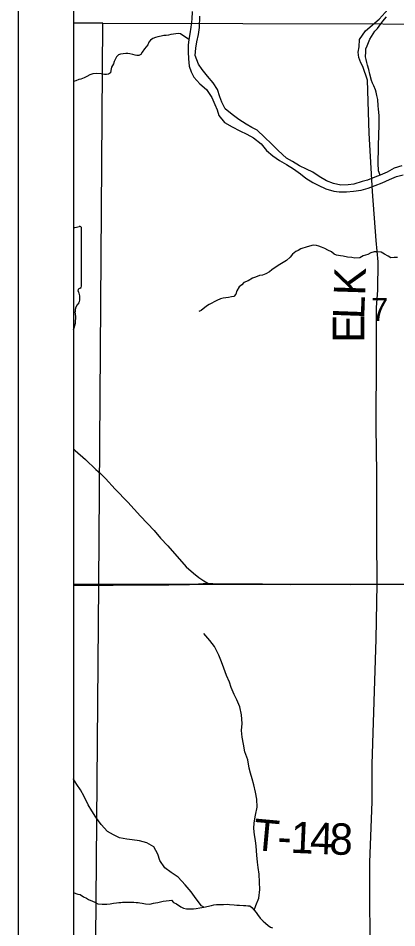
# Model space of a CAD drawing. Extents: x 0 to 34, y 0 to 22.
# Drawn here: x 2 to 2.685, y 18.526 to 20.171 of the extents above; entities that cross this region are included whole.
import ezdxf

# ---------------------------------------------------------------- set-up
doc = ezdxf.new("R2010")
doc.units = 0
for name, color, linetype in [('GM_X_Corporation', 7, 'Continuous'), ('GM_X_County_Road', 7, 'Continuous'), ('GM_X_County_Road_Text', 7, 'Continuous'), ('GM_X_Minor_River', 7, 'Continuous'), ('GM_X_Section_Text', 7, 'Continuous'), ('GM_X_State_Route', 7, 'Continuous'), ('GM_X_State_Shield', 7, 'Continuous'), ('GM_X_Township_Road_Text', 7, 'Continuous'), ('SH_Data', 7, 'Continuous')]:
    doc.layers.add(name, color=color, linetype=linetype)

msp = doc.modelspace()

# ---------------------------------------------------------------- linework, layer by layer
at = {"layer": 'GM_X_Corporation'}
msp.add_lwpolyline([(8.2532, 20.898), (2.1, 20.898), (2.1, 14.098)], dxfattribs=at)
for points in [[(2.1, 20.1616), (2.1, 19.147), (2.1459, 19.1467), (2.1533, 20.1617)], [(3.1676, 20.1592), (3.1497, 19.1471), (2.1459, 19.1467), (2.1533, 20.1617)], [(2.1, 19.147), (2.1, 18.1476), (2.1373, 18.1473), (2.1459, 19.1467)], [(2.1459, 19.1467), (3.1497, 19.1471), (3.1398, 18.1413), (2.1373, 18.1473)]]:
    msp.add_lwpolyline(points, close=True, dxfattribs=at)
at = {"layer": 'GM_X_County_Road'}
for points in [[(2.6495, 19.1471), (2.6493, 19.2335), (2.6492, 19.3478), (2.6482, 19.4317), (2.6487, 19.5612), (2.6486, 19.6474), (2.651, 19.6789), (2.6515, 19.7301), (2.6481, 19.7688), (2.6411, 19.8573), (2.6352, 19.963), (2.632, 20.0588), (2.6239, 20.0833), (2.6201, 20.0901), (2.6167, 20.0998), (2.6153, 20.1094), (2.6169, 20.119), (2.6178, 20.132), (2.6285, 20.1479), (2.6532, 20.1693), (2.6802, 20.1995)], [(2.674, 17.6542), (2.5993, 17.844), (2.5758, 17.9045), (2.5703, 17.9233), (2.5723, 17.9433), (2.6059, 18.0408), (2.6301, 18.1404), (2.6249, 18.205), (2.6178, 18.2367), (2.6206, 18.2704), (2.6317, 18.3484), (2.6345, 18.3799), (2.6342, 18.4007), (2.6368, 18.4443), (2.6367, 18.6447), (2.6405, 18.7534), (2.6409, 18.8215), (2.6479, 19.0479), (2.6495, 19.1471)]]:
    msp.add_lwpolyline(points, dxfattribs=at)
at = {"layer": 'GM_X_Minor_River'}
for points in [[(2.3151, 20.1832), (2.3141, 20.1691), (2.3123, 20.1543), (2.3109, 20.1426), (2.3088, 20.132), (2.3075, 20.1221), (2.3076, 20.1099), (2.3085, 20.0973), (2.3097, 20.084), (2.3133, 20.0737), (2.3177, 20.0641), (2.3288, 20.0524), (2.3407, 20.0416), (2.3503, 20.0277), (2.3557, 20.015), (2.3601, 20.005), (2.3633, 19.9951), (2.3737, 19.9819), (2.3875, 19.9741), (2.401, 19.967), (2.4138, 19.961), (2.4258, 19.9547), (2.4396, 19.9438), (2.4493, 19.9318), (2.4608, 19.922), (2.4732, 19.9134), (2.4859, 19.906), (2.4983, 19.8985), (2.511, 19.8891), (2.5207, 19.8813), (2.5334, 19.8735), (2.5432, 19.8687), (2.5567, 19.862), (2.571, 19.8583), (2.5812, 19.8569), (2.5945, 19.8567), (2.6071, 19.8583), (2.6207, 19.86), (2.6333, 19.8632), (2.6459, 19.8682), (2.6586, 19.8729), (2.672, 19.8791), (2.685, 19.8846), (2.6968, 19.8878)], [(2.6941, 19.9038), (2.6807, 19.8995), (2.6677, 19.8925), (2.655, 19.8867), (2.6455, 19.8831), (2.6325, 19.8776), (2.6226, 19.8752), (2.6073, 19.8709), (2.597, 19.8696), (2.5841, 19.8687), (2.5705, 19.872), (2.5581, 19.8764), (2.5446, 19.8843), (2.533, 19.8925), (2.5221, 19.898), (2.509, 19.9036), (2.4963, 19.9118), (2.4858, 19.9178), (2.4705, 19.9314), (2.4582, 19.9438), (2.4456, 19.9554), (2.4325, 19.9682), (2.4228, 19.9734), (2.4127, 19.9793), (2.3996, 19.9879), (2.3872, 19.9965), (2.3745, 20.007), (2.3683, 20.019), (2.3647, 20.0285), (2.3608, 20.0419), (2.3531, 20.0542), (2.3424, 20.0659), (2.3327, 20.0782), (2.3261, 20.0879), (2.3204, 20.1032), (2.3218, 20.1169), (2.3235, 20.1283), (2.3261, 20.1415), (2.3282, 20.154), (2.3286, 20.1746)], [(2.655, 19.8867), (2.652, 19.8949), (2.6521, 19.8998), (2.6517, 19.904), (2.652, 19.9416), (2.6524, 19.9465), (2.6528, 19.953), (2.6529, 19.9651), (2.6534, 19.9719), (2.6534, 19.9829), (2.6531, 19.989), (2.6531, 19.9951), (2.6521, 20.0061), (2.6514, 20.0126), (2.6507, 20.0236), (2.6489, 20.0308), (2.6478, 20.0373), (2.6467, 20.0414), (2.6437, 20.0483), (2.6415, 20.0533), (2.6396, 20.0582), (2.6367, 20.0696), (2.6345, 20.078), (2.6322, 20.086), (2.6311, 20.0905), (2.6297, 20.0959), (2.6286, 20.1012), (2.629, 20.1099), (2.6294, 20.1156), (2.6314, 20.1209), (2.6364, 20.133), (2.6455, 20.1473), (2.6501, 20.1519), (2.6562, 20.1605), (2.6601, 20.1654), (2.6669, 20.1733)], [(2.3088, 20.132), (2.2939, 20.1425), (2.2905, 20.1429), (2.2855, 20.1427), (2.2809, 20.142), (2.276, 20.1414), (2.2722, 20.1404), (2.2676, 20.1398), (2.2638, 20.1395), (2.2588, 20.1385), (2.253, 20.1371), (2.2488, 20.1361), (2.2438, 20.1343), (2.2396, 20.131), (2.2364, 20.1273), (2.2344, 20.1228), (2.2285, 20.1154), (2.2242, 20.1094), (2.2222, 20.1049), (2.2183, 20.1035), (2.2149, 20.1036), (2.2115, 20.1041), (2.2077, 20.1049), (2.2021, 20.1066), (2.1983, 20.1071), (2.1948, 20.1068), (2.1903, 20.1066), (2.1853, 20.1059), (2.1815, 20.1045), (2.178, 20.1012), (2.1735, 20.0926), (2.1723, 20.0881), (2.1687, 20.0821), (2.1674, 20.0761), (2.1673, 20.0723), (2.1634, 20.0697), (2.1596, 20.0691), (2.1562, 20.0692), (2.1501, 20.0701), (2.1418, 20.0707), (2.1349, 20.0701), (2.1299, 20.0684), (2.1242, 20.0651), (2.1192, 20.063), (2.1134, 20.0605), (2.1099, 20.0598), (2.1046, 20.0577), (2.1, 20.0561)], [(2.6868, 19.7379), (2.6804, 19.7383), (2.6743, 19.7372), (2.6698, 19.7403), (2.6627, 19.7438), (2.657, 19.7476), (2.6491, 19.7481), (2.6442, 19.7481), (2.6381, 19.7463), (2.6328, 19.7433), (2.6244, 19.7411), (2.6184, 19.7377), (2.6093, 19.7371), (2.604, 19.7379), (2.5961, 19.7387), (2.5881, 19.7403), (2.5832, 19.7411), (2.5764, 19.7423), (2.5719, 19.7442), (2.567, 19.7481), (2.5606, 19.7515), (2.5553, 19.7542), (2.5489, 19.7566), (2.5444, 19.7585), (2.5399, 19.7597), (2.5338, 19.7601), (2.5228, 19.7572), (2.5115, 19.7535), (2.5065, 19.7509), (2.5024, 19.7487), (2.4966, 19.7438), (2.4925, 19.7385), (2.4856, 19.7329), (2.4765, 19.7273), (2.4708, 19.7235), (2.459, 19.716), (2.4548, 19.7119), (2.4484, 19.7086), (2.4419, 19.7063), (2.4366, 19.7052), (2.4294, 19.7023), (2.4241, 19.7008), (2.4165, 19.6959), (2.4085, 19.6926), (2.4047, 19.6885), (2.3998, 19.6847), (2.396, 19.6775), (2.394, 19.6719), (2.3902, 19.6677), (2.386, 19.667), (2.3807, 19.6659), (2.3713, 19.6645), (2.366, 19.663), (2.3595, 19.6604), (2.3459, 19.6533), (2.3409, 19.6503), (2.331, 19.6421), (2.3269, 19.6406)], [(2.4272, 18.5575), (2.4299, 18.566), (2.4358, 18.5796), (2.4373, 18.5951), (2.4368, 18.6084), (2.436, 18.6229), (2.4343, 18.6347), (2.4334, 18.6442), (2.4321, 18.6572), (2.4309, 18.6732), (2.4296, 18.6835), (2.4279, 18.6941), (2.4266, 18.7052), (2.4269, 18.7158), (2.4298, 18.7295), (2.4324, 18.7442), (2.4319, 18.7587), (2.4295, 18.7709), (2.4263, 18.7843), (2.4235, 18.795), (2.4203, 18.8053), (2.4182, 18.8148), (2.4155, 18.8293), (2.4105, 18.8443), (2.4081, 18.858), (2.4053, 18.8706), (2.4044, 18.8824), (2.4051, 18.8953), (2.4043, 18.9109), (2.4011, 18.9254), (2.3957, 18.9381), (2.391, 18.948), (2.3855, 18.9603), (2.3827, 18.9699), (2.3769, 18.9822), (2.3722, 18.9952), (2.3679, 19.007), (2.3632, 19.0189), (2.3552, 19.0343), (2.3471, 19.0455), (2.3363, 19.0582)], [(2.336, 18.5634), (2.3316, 18.5653), (2.322, 18.578), (2.3128, 18.5907), (2.3025, 18.6038), (2.2895, 18.6174), (2.2767, 18.626), (2.2655, 18.6342), (2.2563, 18.6473), (2.2527, 18.6588), (2.2458, 18.6722), (2.2327, 18.6793), (2.2195, 18.683), (2.2062, 18.6848), (2.1964, 18.6861), (2.1832, 18.6887), (2.1723, 18.6942), (2.1618, 18.7001), (2.1503, 18.7129), (2.1407, 18.7256), (2.1334, 18.7375), (2.1267, 18.7483), (2.1195, 18.7633), (2.1125, 18.7752), (2.1059, 18.7848), (2.1004, 18.7948), (2.1, 18.7955)], [(2.1, 18.5897), (2.1043, 18.5879), (2.1077, 18.5867), (2.1123, 18.5858), (2.1183, 18.5819), (2.1239, 18.5794), (2.1273, 18.5771), (2.1348, 18.5738), (2.1389, 18.5722), (2.1442, 18.5694), (2.1521, 18.5684), (2.1605, 18.5686), (2.1662, 18.5692), (2.1723, 18.5705), (2.1777, 18.5711), (2.1819, 18.5714), (2.1857, 18.5717), (2.1891, 18.572), (2.1952, 18.5722), (2.202, 18.572), (2.2093, 18.5722), (2.2134, 18.5717), (2.2169, 18.5716)], [(2.2169, 18.5716), (2.2203, 18.5707), (2.2244, 18.5702), (2.2305, 18.5689), (2.2381, 18.5687), (2.245, 18.5701), (2.2488, 18.5711), (2.2526, 18.5717), (2.2625, 18.5737), (2.2679, 18.5747), (2.2732, 18.5753), (2.2774, 18.5756), (2.2811, 18.5717), (2.2868, 18.5693), (2.2946, 18.5638), (2.2991, 18.5614), (2.3048, 18.5604), (2.3093, 18.5599), (2.3128, 18.5599), (2.3173, 18.5601), (2.3223, 18.5607), (2.3288, 18.5617), (2.336, 18.5634), (2.3498, 18.5664), (2.354, 18.5674), (2.359, 18.5677), (2.3628, 18.568), (2.3677, 18.5682), (2.3719, 18.5681), (2.378, 18.5683), (2.3826, 18.5678), (2.3909, 18.5672), (2.3955, 18.5667), (2.4008, 18.5665), (2.408, 18.566), (2.4122, 18.5662), (2.4156, 18.5658), (2.419, 18.5657), (2.4227, 18.5625), (2.4272, 18.5575), (2.4308, 18.5532), (2.4334, 18.5497), (2.4382, 18.5431), (2.4434, 18.5377), (2.4475, 18.5342), (2.4523, 18.5302), (2.4564, 18.5267), (2.4602, 18.5255)]]:
    msp.add_lwpolyline(points, dxfattribs=at)
at = {"layer": 'GM_X_State_Route'}
for points in [[(2.1, 19.3918), (2.1032, 19.389), (2.1218, 19.3725), (2.1407, 19.3545), (2.1487, 19.3475), (2.1578, 19.3384)], [(2.1578, 19.3384), (2.1758, 19.3192), (2.1982, 19.2955), (2.2216, 19.2701), (2.2459, 19.2444), (2.2576, 19.2302), (2.2709, 19.2165), (2.3041, 19.1788), (2.3171, 19.1672), (2.3268, 19.1593), (2.3361, 19.153), (2.3432, 19.1492), (2.3616, 19.1477), (2.3942, 19.1479), (2.4421, 19.1477), (2.4928, 19.1468), (2.5425, 19.1474), (2.6014, 19.1469), (2.6495, 19.1471), (2.6593, 19.147)], [(2.1, 19.1455), (2.1028, 19.1455), (2.1463, 19.1448), (2.1607, 19.1453), (2.1717, 19.1456), (2.1992, 19.1459), (2.2275, 19.1461), (2.2725, 19.1463), (2.3099, 19.1469), (2.3262, 19.1477), (2.3432, 19.1492)], [(2.6593, 19.147), (2.6995, 19.1466)]]:
    msp.add_lwpolyline(points, dxfattribs=at)
at = {"layer": 'GM_X_State_Shield'}
msp.add_line((2.1, 19.7913), (2.1, 19.6071), dxfattribs=at)
msp.add_lwpolyline([(2.1147, 19.686), (2.1147, 19.686), (2.1147, 19.686), (2.1147, 19.7909)], dxfattribs=at)
for centre, major_axis, start_param, end_param in [((1.9973, 20.0586), (0.3495, 0), 5.010524, 5.042369), ((2.1111, 19.7911), (0.00367, 0), 6.197627, 7.989034), ((2.1139, 19.6783), (0.00568, 0), 1.883976, 3.671073), ((2.0778, 19.6651), (0.0341, 0), 5.934695, 6.695948), ((2.1108, 19.6856), (0.00393, 0), 5.054544, 6.418171), ((2.1279, 19.6422), (0.0248, 0), 2.387724, 3.262537), ((2.0169, 19.6289), (0.0874, 0), 5.966942, 6.440018)]:
    msp.add_ellipse(centre, major_axis=major_axis, ratio=0.8, start_param=start_param, end_param=end_param, dxfattribs=at)
at = {"layer": 'SH_Data'}
for p, q in [((2, 20.998), (2, 13.998)), ((2.1, 20.898), (2.1, 14.098))]:
    msp.add_line(p, q, dxfattribs=at)

# ---------------------------------------------------------------- texts
at = {"layer": 'GM_X_County_Road_Text'}
for s, rotation, p in [('K', 88.1437, (2.6278, 19.6687)), ('L', 87.9339, (2.6262, 19.626)), ('E', 89.9293, (2.6262, 19.584))]:
    msp.add_text(s, height=0.0568, rotation=rotation, dxfattribs=at).set_placement(p)
at = {"layer": 'GM_X_Section_Text'}
msp.add_text('7', height=0.0419, rotation=0, dxfattribs=at).set_placement((2.6385, 19.623))
at = {"layer": 'GM_X_Township_Road_Text'}
for s, rotation, p in [('T', 354.8031, (2.4236, 18.6669)), ('1', 357.4838, (2.4921, 18.6616)), ('4', 357.8281, (2.5274, 18.66)), ('8', 357.8997, (2.5625, 18.6587)), ('-', 356.9514, (2.4682, 18.6628))]:
    msp.add_text(s, height=0.0568, rotation=rotation, dxfattribs=at).set_placement(p)

doc.saveas('drawing.dxf')
